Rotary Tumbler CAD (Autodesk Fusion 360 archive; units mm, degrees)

design "Rotary Tumbler" references "Timming belt GT2 200x6", "PL GT2 20 d5 b6", "Headless screw M3x5", "ISO7380-1 M3x8", "Slider T-Nut for 2020 - M5", "Washer DIN 9021 10x5x1", "Pillow Block Bearing P08", "RUTHEX_M3x5_7", "Fixed Axle", "Washer 6x3x.6", "FIDEL", "NEMA17_48", "PL GT2 60 d8 b6", "Headless screw M4x5_8", "Driven Axle", "ISO7380-1 M5x10", "Frame"
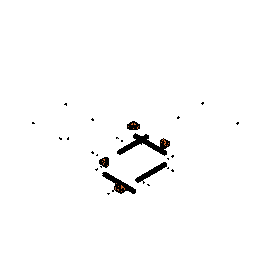
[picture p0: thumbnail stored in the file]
description: Modular rotary tumbler for use with different sized barrels.
description: Pillow Block for fixed axle
part number: FEEBLE
description: Pillow Block for driven axle
part number: ILLEGAL
component_insert "Component Insert1"
component_insert "Component Insert20"
component_insert "Component Insert21"
component_insert "Component Insert22"
component_insert "Component Insert23"
component_insert "Component Insert24"
component_insert "Component Insert25"
component_insert "Component Insert26"
component_insert "Component Insert27"
component_insert "Component Insert28"
joint "Assemble27" alignAngle 90 alignOffsetX 0 alignOffsetY 0 alignOffsetZ 0
joint "Assemble28" alignAngle 0 alignOffsetX 0 alignOffsetY 0 alignOffsetZ 0
joint "Assemble29" alignAngle 0 alignOffsetX 0 alignOffsetY 0 alignOffsetZ 0
joint "Assemble30" alignAngle 0 alignOffsetX 0 alignOffsetY 0 alignOffsetZ 0
joint "Assemble31" alignAngle 0 alignOffsetX 0 alignOffsetY 0 alignOffsetZ 0
joint "Assemble32" alignAngle -90 alignOffsetX 0 alignOffsetY 0 alignOffsetZ 0
joint "Assemble33" alignAngle -90 alignOffsetX 0 alignOffsetY 0 alignOffsetZ 0
joint "Assemble34" alignAngle -90 alignOffsetX 0 alignOffsetY 0 alignOffsetZ 0
joint "Assemble35" alignAngle -90 alignOffsetX 0 alignOffsetY 0 alignOffsetZ 0
component_insert "Component Insert1"
component_insert "Component Insert2"
component_insert "Component Insert3"
joint "Assemble1" alignAngle -90 alignOffsetX 0 alignOffsetY 0 alignOffsetZ -0.4211
joint "Assemble2" alignAngle 90 alignOffsetX 0 alignOffsetY 0 alignOffsetZ -1.3402
component_insert "Component Insert4"
component_insert "Component Insert5"
joint "Assemble3" alignAngle 180 alignOffsetX 0 alignOffsetY 0 alignOffsetZ 0.25
joint "Assemble4" alignAngle 0 alignOffsetX 0 alignOffsetY 0 alignOffsetZ 0.25
joint "Assemble15" alignAngle 0 alignOffsetX 0 alignOffsetY 0 alignOffsetZ 0
component_insert "Component Insert6"
component_insert "Component Insert7"
component_insert "Component Insert8"
component_insert "Component Insert9"
component_insert "Component Insert10"
component_insert "Component Insert11"
joint "Assemble5" alignAngle 0 alignOffsetX 0 alignOffsetY 0 alignOffsetZ 0
joint "Assemble6" alignAngle 0 alignOffsetX 0 alignOffsetY 0 alignOffsetZ 0
joint "Assemble7" alignAngle 0 alignOffsetX 0 alignOffsetY 0 alignOffsetZ 0
joint "Assemble8" alignAngle 0 alignOffsetX 0 alignOffsetY 0 alignOffsetZ 0
joint "Assemble9" alignAngle 90 alignOffsetX 0 alignOffsetY 0 alignOffsetZ 0
joint "Assemble10" alignAngle 90 alignOffsetX 0 alignOffsetY 0 alignOffsetZ 0
copy_paste "CopyPaste1"
joint "Assemble16" alignAngle 0 alignOffsetX 0 alignOffsetY 0 alignOffsetZ 0
component_insert "Component Insert11"
joint "Assemble17" alignAngle 0 alignOffsetX 0 alignOffsetY 0 alignOffsetZ -8
component_insert "Component Insert2"
component_insert "Component Insert3"
component_insert "Component Insert4"
component_insert "Component Insert5"
component_insert "Component Insert6"
component_insert "Component Insert7"
component_insert "Component Insert8"
joint "Assemble1" alignAngle 0 alignOffsetX 0 alignOffsetY 0 alignOffsetZ 0
joint "Assemble2" alignAngle 90 alignOffsetX 0 alignOffsetY 0 alignOffsetZ 0
joint "Assemble3" alignAngle 0 alignOffsetX 0 alignOffsetY 0 alignOffsetZ 0
joint "Assemble4" alignAngle 90 alignOffsetX 0 alignOffsetY 0 alignOffsetZ 0
joint "Assemble5" alignAngle 0 alignOffsetX 0 alignOffsetY 0 alignOffsetZ 0
joint "Assemble6" alignAngle 0 alignOffsetX 0 alignOffsetY 0 alignOffsetZ 0
joint "Assemble18" alignAngle 180 alignOffsetX 0 alignOffsetY 0 alignOffsetZ 1.2
copy_paste "CopyPaste2"
joint "Assemble19" alignAngle 0 alignOffsetX 0 alignOffsetY 0 alignOffsetZ 1.2
component_insert "Component Insert12"
joint "Assemble20" alignAngle 180 alignOffsetX 0 alignOffsetY 0 alignOffsetZ -8
component_insert "Component Insert13"
component_insert "Component Insert14"
joint "Assemble22" alignAngle 3.6 (= "0.6 deg + 3 deg") alignOffsetX 0 alignOffsetY 0 alignOffsetZ -0.8
component_insert "Component Insert15"
component_insert "Component Insert16"
joint "Assemble23" alignAngle 0 alignOffsetX 0 alignOffsetY 0 alignOffsetZ -4
joint "Assemble24" alignAngle -90 alignOffsetX 0 alignOffsetY 0 alignOffsetZ -4
component_insert "Component Insert17"
component_insert "Component Insert18"
joint "Assemble25" alignAngle -90 alignOffsetX 0 alignOffsetY 0 alignOffsetZ 0.8
joint "Assemble26" alignAngle 0 alignOffsetX 0 alignOffsetY 0 alignOffsetZ 0
joint "Assemble36" alignAngle 0 alignOffsetX 0 alignOffsetY 0 alignOffsetZ -1.378
component_insert "Component Insert19"
position "Position1"
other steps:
create_component "CreateComponent2"
create_component "CreateComponent3"

design "Timming belt GT2 200x6"
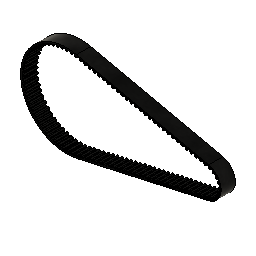
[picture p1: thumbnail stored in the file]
description: Timming Belt GT2x6mm 200 mm
part number: MELT GT2 200
parameter "BeltLength" = 200
parameter "Pitch" = 2
parameter "PulleyDistance" = 58.6379 (= "( ( b + sqrt(( b ^ 2 ) - ( 32 * ( D / mm - d / mm ) ^ 2 )) ) / 16 ) * 1 mm")
sketch "Sketch1" plane through (0, 0, 0) normal (0, 1, 0) x axis (1, 0, 0)
  line L1 (0, -22.5) -> (0, -1.75)
  line L2 (22.5, 0) -> (1.75, 0)
  line L3 (30.7013, -6.2143) -> (-25.172, -18.6429)
  line L4 (30.7013, 6.2143) -> (-25.172, 18.6429)
  arc A1 centre (-29.319, 0) radius 19.0986 clockwise from (-25.172, -18.6429) to (-25.172, 18.6429)
  arc A2 centre (29.319, 0) radius 6.3662 clockwise from (30.7013, 6.2143) to (30.7013, -6.2143)
  point P3 (-29.319, 0)
  point P2 (29.319, 0)
  coincident P3 L2
  coincident P2 L2
  tangent L3 A2
  tangent L4 A2
  tangent L3 A1
  tangent L4 A1
  dimension "d3" distance P2 P3 = 58.6379 (= "PulleyDistance")
  dimension "d4" distance P3 L1 = 29.319 (= "d3 / 2")
  dimension "d5" diameter A1 = 38.1972 (= "Diameter Dimension-2")
  dimension "d6" diameter A2 = 12.7324 (= "Diameter Dimension-3")
sketch "Sketch2" plane through (0, 0, 0) normal (0, 1, 0) x axis (1, 0, 0)
  line L1 (30.7013, -6.2143) -> (-25.172, -18.6429)
  line L2 (30.7013, 6.2143) -> (-25.172, 18.6429)
  line L3 (30.7838, -6.5852) -> (-25.0895, -19.0139)
  line L4 (30.7838, 6.5852) -> (-25.0895, 19.0139)
  line L5 (30.647, 5.9703) -> (-25.2263, 18.3989)
  line L6 (30.647, -5.9703) -> (-25.2263, -18.3989)
  line L7 (22.5, 0) -> (1.75, 0)
  line L8 (-41.8216, 1) -> (-50.6571, 1)
  line L9 (-48.1676, -4.9023) -> (-48.1676, 12.5023)
  line L10 (-48.7976, -4.2002) -> (-48.7976, 7.1002)
  line L11 (-46.8, -0.0031) -> (-50.8, -0.0031)
  line L12 (-48.1676, 0.7402) -> (-48.1676, 1)
  line L13 (-48.1676, 0) -> (-47.4176, -0.0031)
  line L14 (-48.4176, 1) -> (-48.1676, 1)
  line L15 (-47.4176, -0.0031) -> (-48.4176, 0)
  line L16 (-48.4176, -3.8288) -> (-48.4176, -22.7893)
  line L17 (-48.4176, 1) -> (-48.4176, -0.0031)
  line L18 (-48.4176, 15) -> (-48.4176, 3.8288)
  line L19 (-48.4176, -1.0063) -> (-48.4176, -0.0031)
  line L20 (-48.4176, -1.0063) -> (-48.1676, -1.0063)
  line L21 (-48.1676, -0.7465) -> (-48.1676, -1.0063)
  arc A1 centre (-29.319, 0) radius 19.0986 clockwise from (-25.172, -18.6429) to (-25.172, 18.6429)
  arc A2 centre (29.319, 0) radius 6.3662 clockwise from (30.7013, 6.2143) to (30.7013, -6.2143)
  arc A3 centre (29.319, 0) radius 6.7462 clockwise from (30.7838, 6.5852) to (30.7838, -6.5852)
  arc A4 centre (-29.319, 0) radius 19.4786 clockwise from (-25.0895, -19.0139) to (-25.0895, 19.0139)
  arc A5 centre (29.319, 0) radius 6.1162 clockwise from (30.647, 5.9703) to (30.647, -5.9703)
  arc A6 centre (-29.319, 0) radius 18.8486 clockwise from (-25.2263, -18.3989) to (-25.2263, 18.3989)
  arc A7 centre (-48.0176, 0.7402) radius 0.15 clockwise from (-48.0371, 0.5915) to (-48.1676, 0.7402)
  arc A8 centre (-48.1676, -0.4) radius 1 clockwise from (-48.0371, 0.5915) to (-47.7357, 0.502)
  arc A9 centre (-48.1676, -0.4) radius 1 clockwise from (-48.7976, 0.3766) to (-48.7939, 0.3796)
  arc A10 centre (-48.1676, -0.4) radius 1 clockwise from (-48.1676, 0.6) to (-48.158, 0.6)
  arc A11 centre (-48.1676, -0.4) radius 1 clockwise from (-48.4176, 0.5682) to (-48.409, 0.5704)
  arc A12 centre (-47.9776, -0.0031) radius 0.56 clockwise from (-48.1676, 0.5236) to (-48.1602, 0.5262)
  arc A13 centre (-47.9776, -0.0031) radius 0.56 clockwise from (-48.4176, 0.3433) to (-48.4144, 0.3472)
  arc A14 centre (-47.9776, -0.0031) radius 0.56 clockwise from (-48.4143, -0.3537) to (-48.4176, -0.3495)
  arc A15 centre (-47.9776, -0.0031) radius 0.56 clockwise from (-48.16, -0.5326) to (-48.1676, -0.5299)
  arc A16 centre (-47.9776, -0.0031) radius 0.56 clockwise from (-47.7357, 0.502) to (-47.4176, -0.0031)
  arc A17 centre (-48.0176, -0.7465) radius 0.15 clockwise from (-48.1676, -0.7465) to (-48.0371, -0.5977)
  arc A18 centre (-48.1676, 0.3937) radius 1 clockwise from (-47.7357, -0.5082) to (-48.0371, -0.5977)
  arc A19 centre (-47.9776, -0.0031) radius 0.56 clockwise from (-47.4176, -0.0031) to (-47.7357, -0.5082)
  point P32 (-48.1676, -0.4)
  point P38 (-47.9776, -0.0031)
  point P40 (-48.1676, 0.7402)
  point P41 (-48.158, 0.6)
  point P42 (-47.7357, 0.502)
  point P43 (-48.1602, 0.5262)
  point P45 (-48.7976, 0.3766)
  point P46 (-48.4176, 0.5682)
  point P47 (-48.7939, 0.3796)
  point P49 (-48.1676, 0.6)
  point P50 (-48.409, 0.5704)
  point P52 (-48.1676, 0.5236)
  point P53 (-48.4144, 0.3472)
  point P55 (-48.4176, 0.3433)
  point P57 (-48.4176, -0.3495)
  point P58 (-48.4143, -0.3537)
  point P59 (-48.1676, -0.5299)
  point P61 (-48.16, -0.5326)
  point P62 (-47.4176, -0.0031)
  point P64 (-48.1676, 1)
  point P65 (-48.1676, 0)
  point P66 (-48.4176, 1)
  point P67 (-48.4176, 0)
  point P68 (-48.4176, -3.8288)
  point P69 (-48.4176, -0.0031)
  point P70 (-48.4176, 3.8288)
  point P39 (-48.0371, 0.5915)
  point P76 (-48.0371, -0.5977)
  point P74 (-48.1676, -0.7465)
  point P78 (-47.7357, -0.5082)
  point P80 (-47.4176, -0.0031)
  point P73 (-48.1676, -1.0063)
  point P72 (-48.4176, -1.0063)
  point P71 (-48.4176, -0.0031)
  tangent A1 L16
  vertical L16
  perpendicular L8 L16
  parallel L9 L16
  coincident L9 P32
  parallel L10 L16
  tangent L9 A7
  tangent A7 A10
  perpendicular L9 L11
  coincident L11 P38
  tangent A10 A12
  coincident L9 P40
  coincident A6 P41
  coincident P42 A10
  coincident A6 P43
  concentric A8 A10
  coincident L10 P45
  coincident P46 L16
  coincident A4 P47
  concentric A9 A10
  coincident L9 P49
  coincident A1 P50
  concentric A10 A11
  coincident L9 P52
  coincident A1 P53
  concentric A12 A13
  coincident P55 L16
  concentric A13 A14
  coincident P57 L16
  coincident A1 P58
  coincident L9 P59
  concentric A14 A15
  coincident A6 P61
  coincident L11 P62
  concentric A15 A16
  coincident L8 P64
  coincident L9 P64
  midpoint A6 P65
  coincident P66 L16
  coincident L8 P66
  midpoint A1 P67
  coincident A4 P68
  collinear L16 L17
  coincident A1 P69
  coincident A4 P70
  collinear L17 L18
  symmetric L11 P39 P76
  symmetric L11 A7 A17
  symmetric L11 P40 P74
  symmetric L11 P42 P78
  symmetric L11 A8 A18
  symmetric L11 P62 P80
  symmetric L11 A16 A19
  symmetric L11 P64 P73
  symmetric L11 P66 P72
  symmetric L11 P69 P71
  dimension "d15" = 0.38 (= "d21 - 0.25 mm")
  dimension "d16" = -0.25
  dimension "d17" distance L7 L8 = 1
  dimension "d18" distance L9 L16 = 0.25
  dimension "d19" diameter A10 = 2
  dimension "d20" distance L7 P32 = 0.4
  dimension "d21" distance L9 L10 = 0.63 (= "1.38 mm - 0.75 mm")
  dimension "d22" diameter A7 = 0.3 (= "( 0.15 * 2 ) * 1 mm")
  dimension "d23" diameter A12 = 1.12 (= "( 0.56 * 2 ) * 1 mm")
  dimension "d24" distance L9 P38 = 0.19 (= "0.75 mm - d23 / 2")
extrude "Extrude1" new body sketch "Sketch2" profile of A6 L18 A11 A7 A16 L12 L13 L14 L15 L19 L20 L21 A17 A18 A19 distance 3
path_pattern "PathPattern1" countU 100 PathPatternDelta 2
extrude "Extrude2" add sketch "Sketch2" profile of A4 L4 A3 L3 A6 L6 A5 L5 L18 A7 L12 L14 L19 L20 L21 A17 distance 3
position "Position1"
position "Position2"
position "Position3"
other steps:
create_component "CreateComponent1"

design "NEMA17_48"
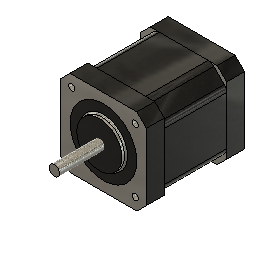
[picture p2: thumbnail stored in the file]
description: Stepper Motor NEMA 17
part number: SERMON 17

design "Nut  M8x6"
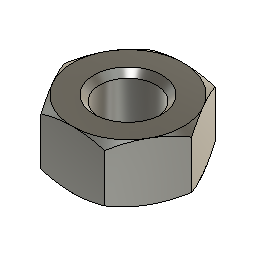
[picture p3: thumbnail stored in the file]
description: Hexagon nut M8
part number: HUT 8
base_feature "Base Feature"

design "V-Slot 20x20x270"
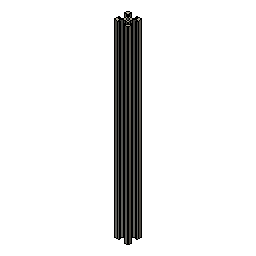
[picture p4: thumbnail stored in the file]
description: Aluminium profile V-Slot 20x20x270
part number: APOLLO 20x20x270
base_feature "Base Feature"

design "Bearing 608"
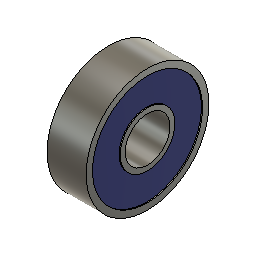
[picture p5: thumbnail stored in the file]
description: Ball bearing 608
part number: BABE 608

design "ISO7380-1 M5x10"
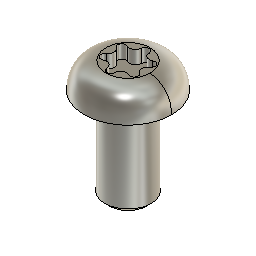
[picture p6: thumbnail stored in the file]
description: TORX pan head screw, ISO7380-1 M5x10
part number: PHASE 5x10
base_feature "Base Feature"

design "FIDEL"
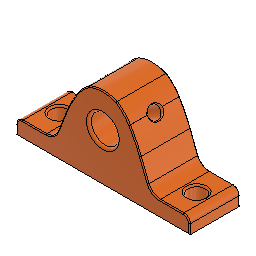
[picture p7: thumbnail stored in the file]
description: 3D printed bearing block with screews, nuts and washers
part number: FIDEL
sketch "Sketch1" plane through (0, 0, 0) normal (0, 1, 0) x axis (1, 0, 0)
  line L1 (-27.5, -3) -> (-27.5, 0)
  line L2 (27.5, 0) -> (27.5, -3)
  line L3 (-27.5, -5) -> (27.5, 0)
  line L4 (27.5, -5) -> (-27.5, 0)
  line L5 (0, -22.5) -> (0, -1.75)
  line L6 (-18.052, -5) -> (-25.5, -5)
  line L7 (25.5, -5) -> (18.052, -5)
  line L8 (-10.5236, -17.3547) -> (-6.8607, -23.3199)
  line L9 (-6.131, 0) -> (-14.131, 0)
  line L10 (-6.131, 0.5) -> (-6.131, 0)
  line L11 (-12.131, 2.5) -> (-8.131, 2.5)
  line L12 (-14.131, 0) -> (-14.131, 0.5)
  line L13 (-12.131, 2.5) -> (-14.131, 0.5)
  line L14 (-6.131, 0.5) -> (-8.131, 2.5)
  line L15 (14.131, 0) -> (14.131, 0.5)
  line L16 (12.131, 2.5) -> (14.131, 0.5)
  line L17 (12.131, 2.5) -> (8.131, 2.5)
  line L18 (6.131, 0.5) -> (8.131, 2.5)
  line L19 (6.131, 0.5) -> (6.131, 0)
  line L20 (0, 0) -> (-27.5, 0)
  line L21 (0, 0) -> (27.5, 0)
  line L22 (-6.8607, -23.3199) -> (-4.3054, -25.0137)
  line L23 (-14.3657, -7.4471) -> (-10.5236, -17.3547)
  line L24 (6.8607, -23.3199) -> (4.3054, -25.0137)
  line L25 (10.5236, -17.3547) -> (6.8607, -23.3199)
  line L26 (14.3657, -7.4471) -> (10.5236, -17.3547)
  line L27 (0, -15) -> (-8.6921, -20.3373)
  circle C1 centre (0, -15) radius 4.4
  arc A1 centre (0, -15) radius 10.9 clockwise from (4.3054, -25.0137) to (-4.3054, -25.0137)
  arc A2 centre (-25.5, -3) radius 2 clockwise from (-25.5, -5) to (-27.5, -3)
  arc A3 centre (25.5, -3) radius 2 clockwise from (27.5, -3) to (25.5, -5)
  arc A4 centre (-18.052, -9) radius 4 clockwise from (-18.052, -5) to (-14.3657, -7.4471)
  arc A5 centre (18.052, -9) radius 4 clockwise from (14.3657, -7.4471) to (18.052, -5)
  point P9 (0, -2.5)
  point P7 (-27.5, -5)
  point P8 (27.5, -5)
  point P24 (-14.131, 2.5)
  point P23 (-6.131, 2.5)
  point P21 (-14.131, 0)
  point P30 (14.131, 0)
  point P22 (-6.131, 0)
  point P34 (6.131, 0)
  point P25 (-14.131, 0.5)
  point P29 (14.131, 0.5)
  point P26 (-12.131, 2.5)
  point P31 (12.131, 2.5)
  point P27 (-8.131, 2.5)
  point P32 (8.131, 2.5)
  point P28 (-6.131, 0.5)
  point P33 (6.131, 0.5)
  point P36 (-18.052, -5)
  point P39 (18.052, -5)
  point P14 (-4.3054, -25.0137)
  point P40 (4.3054, -25.0137)
  point P43 (18.052, -5)
  point P37 (-14.3657, -7.4471)
  point P41 (14.3657, -7.4471)
  point P3 (0, 0)
  point P44 (0, 0)
  point P45 (0, 0)
  point P12 (-6.8607, -23.3199)
  point P47 (-6.8607, -23.3199)
  point P13 (-10.5236, -17.3547)
  point P51 (10.5236, -17.3547)
  point P48 (4.3054, -25.0137)
  point P52 (14.3657, -7.4471)
  point P46 (-6.8607, -23.3199)
  point P50 (6.8607, -23.3199)
  point P49 (6.8607, -23.3199)
  point P35 (-8.6921, -20.3373)
  point P53 (-8.6921, -20.3373)
  point P4 (0, -15)
  point P54 (0, -15)
  point P1 (0, 0)
  point P2 (0, -15)
  point P6 (-27.5, 0)
  parallel L1 L2
  coincident L3 P9
  coincident L4 P9
  concentric C1 A1
  collinear L6 L7
  coincident P7 L6
  coincident P7 L1
  tangent L6 A2
  tangent L1 A2
  coincident P8 L7
  coincident P8 L2
  tangent L7 A3
  tangent L2 A3
  horizontal L9
  vertical L10
  horizontal L11
  vertical L12
  coincident P24 L12
  coincident P24 L11
  coincident P23 L11
  coincident P23 L10
  symmetric L5 P21 P30
  symmetric L5 P22 P34
  symmetric L5 P25 P29
  symmetric L5 P26 P31
  symmetric L5 P27 P32
  symmetric L5 P28 P33
  tangent L6 A4
  symmetric L5 P36 P39
  symmetric L5 P14 P40
  symmetric L5 P36 P43
  symmetric L5 P37 P41
  symmetric L5 A4 A5
  coincident P3 P44
  perpendicular L1 L20
  coincident P3 P45
  perpendicular L5 L21
  coincident P9 L5
  coincident P12 P47
  symmetric L5 P13 P51
  symmetric L5 P14 P48
  symmetric L5 P37 P52
  symmetric L5 P46 P50
  symmetric L5 P47 P49
  midpoint L8 P35
  coincident P35 P53
  coincident P4 P54
  perpendicular L8 L27
  coincident P12 P46
  dimension "d1" diameter C1 = 8.8
  dimension "d2" distance P1 P2 = 15
  dimension "d4" distance P7 P8 = 55
  dimension "d5" distance P6 P7 = 5
  dimension "d10" distance C1 A1 = 6.5
  dimension "d14" distance P12 P13 = 7
  dimension "d24" radius A2 = 2
  dimension "d25" radius A3 = 2
  dimension "d26" distance P21 P22 = 8
  dimension "d27" distance P21 P24 = 2.5
  dimension "d28" distance P24 P25 = 2
  dimension "d29" distance P24 P26 = 2 (= "d28")
  dimension "d30" distance P23 P27 = 2
  dimension "d31" distance P23 P28 = 2 (= "d30")
  dimension "d64" radius A4 = 4
  dimension "d98" distance P53 P54 = 10.2 (= "d1 / 2 + 5.8 mm")
extrude "Extrude1" new body sketch "Sketch1" profile of C1 L1 L7 L2 A1 L8 A2 A3 L9 distance 8
extrude "Extrude2" add sketch "Sketch1" profile of L9 L10 L11 L12 L13 L14 L15 L16 L17 L18 L19 L20 L21 distance 2.9
hole "Hole1" HoleDepth 12 HoleDiameter 5.5 TipAngle 118
fillet "Fillet1" radius 0.5
mirror "Mirror1" mirrorStitchTolerance 0.1
work_point "WorkPoint1"
hole "Hole2" HoleDepth 7 HoleDiameter 3.95 TipAngle 180
fillet "Fillet2" radius 0.5
mirror "Mirror2" mirrorStitchTolerance 0.1
fillet "Fillet3" radius 0.8
fillet "Fillet4" radius 14
fillet "Fillet5" radius 0.5
fillet "Fillet6" radius 43
fillet "Fillet7" radius 0.3
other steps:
step "Assemble4" alignAngle 0 alignOffsetX 0 alignOffsetY 0 alignOffsetZ 6.3
step "Assemble5" alignAngle 180 alignOffsetX 0 alignOffsetY 0 alignOffsetZ 6.2
step "Assemble6" alignAngle 0 alignOffsetX 0 alignOffsetY 0 alignOffsetZ 0
step "Assemble7" alignAngle -90 alignOffsetX 0 alignOffsetY 0 alignOffsetZ 0
step "Assemble8" alignAngle 0 alignOffsetX 0 alignOffsetY 0 alignOffsetZ 1
step "JointOrigin4"
step "Assemble9" alignAngle 0 alignOffsetX 0 alignOffsetY 0 alignOffsetZ 1
step "JointOrigin5"

design "Slider T-Nut for 2020 - M5"
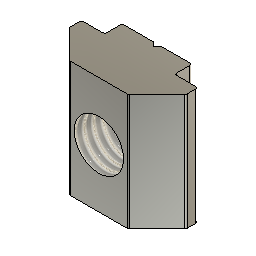
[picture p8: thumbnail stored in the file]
description: Sliding block for T-nut 20 M5
part number: SILO T20/5
sketch "Sketch1" plane through (0, 0, 0) normal (0, 0, 1) x axis (1, 0, 0)
  line L1 (7.4595, 0) -> (2.6252, 0)
  line L2 (10.0424, 3.3) -> (10.0424, 2.5828)
  line L3 (0.0424, 2.5828) -> (0.0424, 3.3)
  line L4 (8.0424, 4.8) -> (8.0424, 3.7)
  line L5 (2.0424, 3.7) -> (2.0424, 4.8)
  line L6 (2.4838, 0.0586) -> (0.101, 2.4414)
  line L7 (3.5052, 2.5) -> (0.0424, 2.5)
  line L8 (5.0424, 0) -> (5.0424, 3.5)
  line L9 (7.601, 0.0586) -> (9.9838, 2.4414)
  line L10 (8.2424, 3.5) -> (9.8424, 3.5)
  line L11 (0.2424, 3.5) -> (1.8424, 3.5)
  line L12 (5.3424, 5) -> (5.0424, 4.7)
  line L13 (6.213, 4.7) -> (5.0424, 4.7)
  line L14 (4.7424, 5) -> (5.0424, 4.7)
  line L15 (6.2088, 4.7) -> (5.0424, 4.7)
  line L16 (5.3424, 5) -> (7.8424, 5)
  line L17 (2.2424, 5) -> (4.7424, 5)
  arc A1 centre (0.2424, 3.3) radius 0.2 clockwise from (0.0424, 3.3) to (0.2424, 3.5)
  arc A2 centre (0.2424, 2.5828) radius 0.2 clockwise from (0.101, 2.4414) to (0.0424, 2.5828)
  arc A3 centre (2.6252, 0.2) radius 0.2 clockwise from (2.6252, 0) to (2.4838, 0.0586)
  arc A4 centre (7.4595, 0.2) radius 0.2 clockwise from (7.601, 0.0586) to (7.4595, 0)
  arc A5 centre (9.8424, 2.5828) radius 0.2 clockwise from (10.0424, 2.5828) to (9.9838, 2.4414)
  arc A6 centre (9.8424, 3.3) radius 0.2 clockwise from (9.8424, 3.5) to (10.0424, 3.3)
  arc A7 centre (8.2424, 3.7) radius 0.2 clockwise from (8.2424, 3.5) to (8.0424, 3.7)
  arc A8 centre (7.8424, 4.8) radius 0.2 clockwise from (7.8424, 5) to (8.0424, 4.8)
  arc A9 centre (2.2424, 4.8) radius 0.2 clockwise from (2.0424, 4.8) to (2.2424, 5)
  arc A10 centre (1.8424, 3.7) radius 0.2 clockwise from (2.0424, 3.7) to (1.8424, 3.5)
  point P4 (2.0424, 3.5)
  point P10 (5.0424, 0)
  point P8 (2.5424, 0)
  point P11 (7.5424, 0)
  point P3 (0.0424, 3.5)
  point P6 (0.0424, 2.5)
  point P2 (10.0424, 3.5)
  point P5 (8.0424, 3.5)
  point P12 (5.0424, 4.7)
  point P16 (4.7424, 5)
  horizontal L1
  vertical L2
  horizontal L10
  vertical L3
  vertical L4
  horizontal L16
  vertical L5
  coincident P4 L10
  horizontal L7
  coincident L1 P10
  perpendicular L1 L8
  symmetric P8 L8 P11
  collinear L10 L11
  horizontal L13
  perpendicular L12 L14
  horizontal L15
  collinear L16 L17
  coincident P3 L3
  coincident P3 L11
  tangent L3 A1
  tangent L11 A1
  coincident P6 L6
  coincident L3 P6
  tangent L6 A2
  tangent L3 A2
  equal A1 A2
  coincident L6 P8
  tangent L6 A3
  tangent L1 A3
  equal A1 A3
  coincident L1 P11
  coincident P11 L9
  tangent L1 A4
  tangent L9 A4
  equal A1 A4
  tangent L9 A5
  tangent L2 A5
  equal A1 A5
  coincident P2 L2
  coincident P2 L10
  tangent L2 A6
  tangent L10 A6
  equal A1 A6
  coincident P5 L10
  coincident P5 L4
  tangent L10 A7
  tangent L4 A7
  equal A1 A7
  tangent L4 A8
  tangent L16 A8
  equal A1 A8
  tangent L17 A9
  tangent L5 A9
  equal A1 A9
  coincident P4 L5
  tangent L11 A10
  tangent L5 A10
  equal A1 A10
  dimension "d1" distance L2 L3 = 10
  dimension "d4" distance L1 L16 = 5
  dimension "d5" angle L6 L7 = 45
  dimension "d6" distance P6 L10 = 1
  dimension "d7" distance P8 P11 = 5
  dimension "d8" distance L4 L5 = 6
  dimension "d9" distance P3 P4 = 2
  dimension "d10" distance P2 P5 = 2
  dimension "d12" angle L12 L13 = 45
  dimension "d13" distance P12 P16 = 0.3
  dimension "d14" distance L1 L17 = 5
  dimension "d15" distance L11 L17 = 1.5
  dimension "d16" radius A1 = 0.2
extrude "Extrude1" new body sketch "Sketch1" profile of L1 L2 L11 L3 L4 L17 L5 L6 L9 L12 L14 A1 A2 A3 A4 A5 A6 A7 A8 A9 A10 along normal blind 10
hole "Hole1" HoleDepth 5.834 HoleDiameter 4.234 TipAngle 180 CSDiameter 6 CSAngle 90 RefDim1 5 RefDim2 5
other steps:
thread "Thread1"

design "Washer DIN 9021 10x5x1"
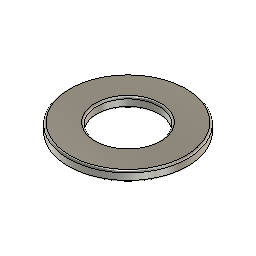
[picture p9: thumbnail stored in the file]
description: Washer DIN 9021  10x5x1
part number: WARD 10x5x1
cylinder_primitive "CylinderPrimitive1" Height 0.85 Diameter 10
cylinder_primitive "CylinderPrimitive2" Height -1 Diameter 5.2
fillet "Fillet1" radius 0.15

design "Driven Axle" references "O-Ring", "Nut  M8x6", "Threaded rod M8x320", "DRIVEL"
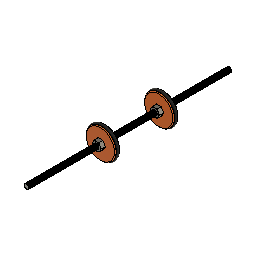
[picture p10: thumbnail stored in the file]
description: Driven Axle Assembly
part number: DIALS
description: Drive Wheel Assembly
part number: REHAB
component_insert "Component Insert1"
component_insert "Component Insert1"
component_insert "Component Insert2"
component_insert "Component Insert3"
as_built_joint "As-built1"
joint "Assemble1" alignAngle 0 alignOffsetX 0 alignOffsetY 0 alignOffsetZ -117
copy_paste "CopyPaste1"
joint "Assemble2" alignAngle 0 alignOffsetX 0 alignOffsetY 0 alignOffsetZ -209 (= "-238 mm + 29 mm")
component_insert "Component Insert2"
component_insert "Component Insert3"
component_insert "Component Insert4"
component_insert "Component Insert5"
joint "Assemble3" alignAngle 0 alignOffsetX 0 alignOffsetY 0 alignOffsetZ 0
joint "Assemble4" alignAngle 0 alignOffsetX 0 alignOffsetY 0 alignOffsetZ 0
joint "Assemble5" alignAngle 0 alignOffsetX 0 alignOffsetY 0 alignOffsetZ 0
joint "Assemble6" alignAngle 0 alignOffsetX 0 alignOffsetY 0 alignOffsetZ 0
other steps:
create_component "CreateComponent1"

design "PL GT2 60 d8 b6"
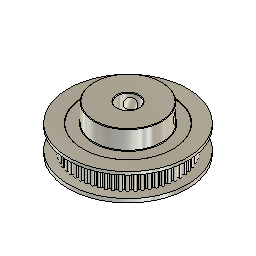
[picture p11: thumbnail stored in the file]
description: Pulley 60 teeth for GT2 timming belt
part number: TIMELY GT2 60x6
base_feature "Base Feature"

design "V-Slot 20x20x250"
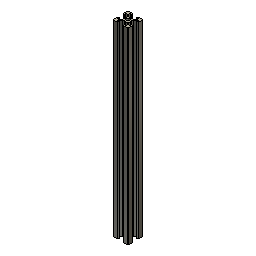
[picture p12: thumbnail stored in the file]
description: Aluminium profile V-Slot 20x20x250
part number: APOLLO 20x20x250
base_feature "Base Feature"

design "Headless screw M4x5_8"
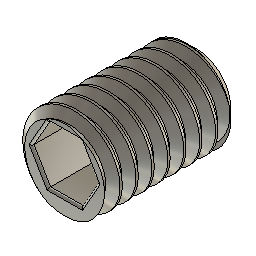
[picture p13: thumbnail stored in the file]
description: Headless screw M4 x 5,8
part number: HADES 4x5_8
base_feature "Base Feature"
sketch "Sketch1" plane through (0, 0, 0) normal (0, 1, 0) x axis (1, 0, 0)
  line L1 (0.7302, 1.2451) -> (1.4433, -0.0098)
  line L2 (-0.7132, 1.2549) -> (0.7302, 1.2451)
  line L3 (-1.4433, 0.0098) -> (-0.7132, 1.2549)
  line L4 (-0.7302, -1.2451) -> (-1.4433, 0.0098)
  line L5 (0.7132, -1.2549) -> (-0.7302, -1.2451)
  line L6 (1.4433, -0.0098) -> (0.7132, -1.2549)
  circle C1 centre (0, 0) radius 2
  point P1 (0, 0)
  point P2 (0, 0)
  point P9 (0, 0)
  coincident P1 P2
  coincident P2 P9
  dimension "d69" diameter C1 = 4
  dimension "d70" distance P9 L6 = 1.25
extrude "Extrude1" new body sketch "Sketch1" along normal blind 5.8
extrude "Extrude2" cut sketch "Sketch1" profile of L1 L2 L3 L4 L5 L6 along normal blind 2.9
chamfer "Chamfer1" distance 0.5
thread "Thread1"
fillet "Fillet1" radius 0.1
move "Move1"

design "PL GT2 20 d5 b6"
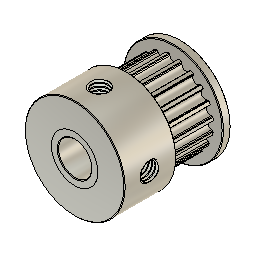
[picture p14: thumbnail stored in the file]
description: Pulley 20 teeth for GT2 timming belt
part number: TIMELY GT2 20x6
base_feature "Base Feature"

design "RUTHEX_M3x5_7"
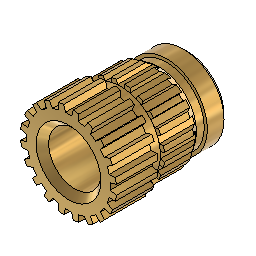
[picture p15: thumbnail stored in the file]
description: RUTHEX fusible thread M3x5,7
part number: REFUTE 3x5,7
base_feature "Base Feature"

design "Pillow Block Bearing P08"
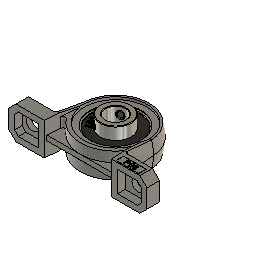
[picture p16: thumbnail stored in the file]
description: Pillow Block Bearing P08
part number: PILE 08
base_feature "Base Feature1"
base_feature "Base Feature1"
as_built_joint "As-built1"
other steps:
create_component "CreateComponent1"
create_component "CreateComponent2"

design "OCEAN 17 2020"
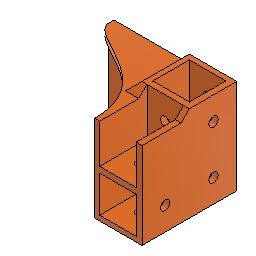
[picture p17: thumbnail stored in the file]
description: 3D printed corner connector for 2020 profiles with integrated NEMA 17 mount
part number: OCEAN 17 2020
base_feature "Base Feature" bodies "2020 2-Way"
offset_faces "OffsetFaces1" distance 3
work_plane "WorkPlane1" AlongDistance 3.2
sketch "Sketch1" plane through (-163, 0, 0) normal (-1, 0, 0) x axis (0, -1, 0)
  line L1 (66.0257, 50) -> (66.0257, 23.5)
  line L2 (39.5257, 50) -> (66.0257, 50)
  line L3 (39.5257, -3) -> (39.5257, 50)
  line L4 (92.5257, -3) -> (39.5257, -3)
  line L5 (92.5257, 23.5) -> (92.5257, -3)
  line L6 (66.0257, 23.5) -> (92.5257, 23.5)
  line L7 (42.5257, -3) -> (42.5257, 50)
  line L8 (92.5257, 50) -> (42.5257, 50)
  line L9 (92.5257, 50) -> (92.5257, -3)
  line L10 (92.5257, 40.326) -> (83.2337, 50)
  point P9 (42.5257, -3)
  point P6 (92.5257, -3)
  point P10 (92.5257, -3)
  point P13 (92.5257, 40.326)
  parallel L3 L7
  coincident L4 P9
  perpendicular L1 L8
  coincident P6 P10
  perpendicular L8 L9
  coincident L9 P13
extrude "Extrude1" add sketch "Sketch1" profile of L2 L3 L4 L7 along a picked direction to an object
sketch "Sketch2" plane through (0, 0, -3) normal (0, 0, -1) x axis (1, 0, 0)
  line L1 (-136.5, 92.5257) -> (-136.5, 39.5257)
  line L2 (-163, 92.5257) -> (-136.5, 92.5257)
  line L3 (-163, 42.5257) -> (-163, 92.5257)
  line L4 (-205.2, 42.5257) -> (-163, 42.5257)
  line L5 (-205.2, 39.5257) -> (-205.2, 42.5257)
  line L6 (-136.5, 39.5257) -> (-205.2, 39.5257)
  curve K1 (-163, 92.5257) -> (-205.2, 42.5257)
  curve K2 (-205.2, 46) -> (-205.2, 39.0514)
  curve K3 (-162.9977, 99.7061) -> (-163.0023, 85.3453)
  circle C1 centre (-150, 79.5257) radius 2.6
  circle C2 centre (-150, 52.5257) radius 2.6
  point P8 (-205.2, 42.5257)
  point P10 (-205.2, 42.5257)
  point P6 (-163, 92.5257)
  point P12 (-163, 92.5257)
  coincident P8 P10
  coincident P6 P12
  midpoint P10 K2
  midpoint P12 K3
extrude "Extrude2" add sketch "Sketch2" profile of L3 L4 K1 along a picked direction blind -3 named "d108_1"
work_plane "WorkPlane2"
mirror "Mirror1" mirrorStitchTolerance 0.1 named "d111_1"
split "Split1" bodies "2020 2-Way (1)"
extrude "Extrude3" cut of existing geometry to an object
combine "Combine1" bodies "2020 2-Way (1)"
extrude "Extrude4" cut of existing geometry blind -3 named "d114_1"
box_primitive "BoxPrimitive1" DistanceX 45.4 named "d116_1" DistanceY 26.5257 named "d117_1" DistanceZ -2.8 named "d118_1" OffsetDistanceX 0 named "d119_1" OffsetDistanceY 0 named "d120_1"
sketch "Sketch4" plane through (0, -39.5257, 0) normal (0, 1, 0) x axis (-1, 0, 0)
  line L1 (136.5, -3) -> (136.5, 50)
  line L2 (205.2, -3) -> (136.5, -3)
  line L3 (205.2, 45.4) -> (205.2, -3)
  line L4 (163, 45.4) -> (205.2, 45.4)
  line L5 (163, 50) -> (163, 45.4)
  line L6 (136.5, 50) -> (163, 50)
  line L7 (205.2, 4.836) -> (200.564, 0.2)
  line L8 (205.2, 37.564) -> (205.2, 4.836)
  line L9 (200.564, 42.2) -> (205.2, 37.564)
  line L10 (167.836, 42.2) -> (200.564, 42.2)
  line L11 (163.2, 37.564) -> (167.836, 42.2)
  line L12 (163.2, 4.836) -> (163.2, 37.564)
  line L13 (167.836, 0.2) -> (163.2, 4.836)
  line L14 (200.564, 0.2) -> (167.836, 0.2)
  circle C1 centre (150, 37) radius 2.6
  circle C2 centre (150, 10) radius 2.6
  circle C3 centre (168.7, 36.7) radius 1.5
  circle C4 centre (168.7, 5.7) radius 1.5
  circle C5 centre (199.7, 5.7) radius 1.5
  circle C6 centre (199.7, 36.7) radius 1.5
  circle C7 centre (199.7, 36.7) radius 1.7
  circle C8 centre (199.7, 5.7) radius 1.7
  circle C9 centre (168.7, 36.7) radius 1.7
  circle C10 centre (168.7, 5.7) radius 1.7
  circle C11 centre (184.2, 21.2) radius 11.75
  circle C12 centre (184.2, 21.2) radius 12.35
  dimension "d121_1" = 0.2
  dimension "d122_1" = 0.2 (= "d121_1")
  dimension "d123_1" = 0.2 (= "d121_1")
  dimension "d124_1" = 0.2 (= "d121_1")
  dimension "d129_1" = 0.6
extrude "Extrude5" cut sketch "Sketch4" profile of C7 C8 C9 C10 C12 blind -3 named "d126_1"
chamfer "Chamfer1" distance 4.6 named "d131_1"
chamfer "Chamfer2" distance 4.6 named "d132_1"
extrude "Extrude6" cut of existing geometry blind -3 named "d133_1"
sketch "Sketch6" plane through (-136.5, 0, 0) normal (1, 0, 0) x axis (0, 1, 0)
  line L1 (-66.0257, 23.5) -> (-66.0257, 50)
  line L2 (-92.5257, 23.5) -> (-66.0257, 23.5)
  line L3 (-92.5257, -3) -> (-92.5257, 23.5)
  line L4 (-39.5257, -3) -> (-92.5257, -3)
  line L5 (-39.5257, 50) -> (-39.5257, -3)
  line L6 (-66.0257, 50) -> (-39.5257, 50)
  line L7 (-66.0257, 50) -> (-70.6257, 45.4)
  line L8 (-92.5257, 45.4) -> (-70.6257, 45.4)
  line L9 (-92.5257, 23.5) -> (-92.5257, 45.4)
  circle C1 centre (-52.5257, 10) radius 2.6
  circle C2 centre (-79.5257, 10) radius 2.6
  circle C3 centre (-52.5257, 37) radius 2.6
extrude "Extrude7" add sketch "Sketch6" profile of L1 L2 L7 L8 L9 along a picked direction to an object
named bodies: "2020 2-Way", "2020 2-Way (1)"

design "REEL"
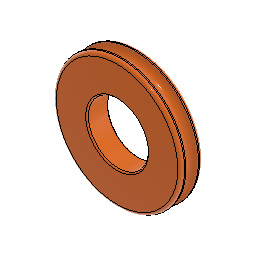
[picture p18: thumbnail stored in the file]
description: 3D printed idler wheel
part number: REEL
base_feature "Base Feature"

design "Threaded rod M8x320"
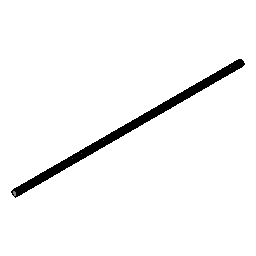
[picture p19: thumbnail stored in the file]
description: Threaded Rod M8x320
part number: TREAD 8x320
cylinder_primitive "CylinderPrimitive1" Height 320 Diameter 8
thread "Thread2"

design "Headless screw M3x5"
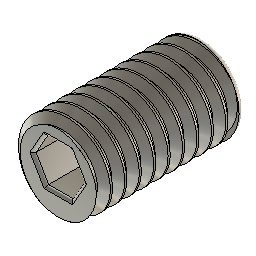
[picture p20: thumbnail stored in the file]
description: Headless screw M3x5
part number: HADES 3x5
sketch "Sketch1" plane through (0, 0, 0) normal (0, 1, 0) x axis (1, 0, 0)
  line L1 (-0.4297, 0.7519) -> (0.4363, 0.7481)
  line L2 (-0.866, 0.0039) -> (-0.4297, 0.7519)
  line L3 (-0.4363, -0.7481) -> (-0.866, 0.0039)
  line L4 (0.4297, -0.7519) -> (-0.4363, -0.7481)
  line L5 (0.866, -0.0039) -> (0.4297, -0.7519)
  line L6 (0.4363, 0.7481) -> (0.866, -0.0039)
  circle C1 centre (0, 0) radius 1.5
  point P1 (0, 0)
  point P2 (0, 0)
  point P9 (0, 0)
  coincident P1 P2
  coincident P1 P9
  dimension "d1" diameter C1 = 3
  dimension "d2" distance P2 L6 = 0.75
extrude "Extrude1" new body sketch "Sketch1" along normal blind 5
extrude "Extrude2" cut sketch "Sketch1" profile of L1 L2 L3 L4 L5 L6 along normal blind 2
fillet "Fillet1" radius 0.1
fillet "Fillet2" radius 0.2
thread "Thread1"

design "OREO 2020"
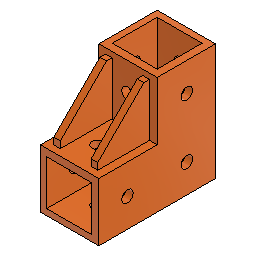
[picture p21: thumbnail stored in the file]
description: 3D printed corner connector for 20x20
part number: OREO 2020
base_feature "Base Feature" bodies "2020 2-Way"
named bodies: "2020 2-Way"

design "O-Ring"
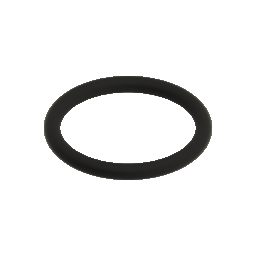
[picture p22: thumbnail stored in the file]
description: Gasket Ring (O-Ring) OD 50 x ID 40x 5
part number: GAIN 50x40x5
sketch "Sketch1" plane through (0, 0, 0) normal (0, 1, 0) x axis (1, 0, 0)
  circle C1 centre (-22.5, 0) radius 2.5
  point P1 (0, 0)
  point P2 (-22.5, 0)
  dimension "d1" diameter C1 = 5
  dimension "d2" distance P1 P2 = 22.5 (= "25 mm - ( d1 / 2 )")
revolve "Revolve1" sketch "Sketch1" AlongAngle 360

design "ISO7380-1 M3x8"
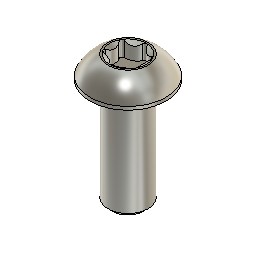
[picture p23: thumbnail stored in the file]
description: TORX pan head screw, ISO7380-1 M3x8
part number: PHASE M3x8
base_feature "Base Feature"
work_plane "WorkPlane1" AlongDistance -0.321
split "Split1"
move "Move1"
offset_faces "OffsetFaces1" distance 2
combine "Combine1"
